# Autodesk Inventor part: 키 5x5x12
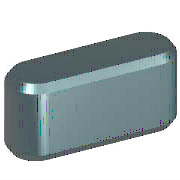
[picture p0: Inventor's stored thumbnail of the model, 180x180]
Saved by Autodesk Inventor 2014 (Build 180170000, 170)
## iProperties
IsCustomPart: 1
Created: 2012-02
Part Number: 키 5x5x12
Material: 강철, 연강
Description: 키 및 해당 키홈
Document SubType Name: Modeling
Standard: KS B 1311
Designer: mduedu
Standards Organization: KS
Language: ko-KR
Size Designation: 5 x 5 x 12
Categories: <MemberInstance><Categories><Category DisplayName="샤프트 부품" InternalName="7f7aeb1f-a693-4053-b835-cee3144e0d98" Mnemonic="SHFT"><Category DisplayName="키" Interna
Density: 1 g/cm^3
Appearance: Yellow
Author: mduedu
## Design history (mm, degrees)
sketch "스케치1"
  geometry: L1 (2.5, 2.5)-(9.5, 2.5); L2 (9.5, -2.5)-(2.5, -2.5); L3 (0, 9.4)-(0, -7.4) reference; L4 (-5, 0)-(30, 0) reference; L5 (12, 0)-(12, 7); A1 r 2.5 centre (2.5, 0) between (2.5, 2.5) and (2.5, -2.5); A2 r 2.5 centre (9.5, 0) between (9.5, -2.5) and (9.5, 2.5)
  constraints: 6 end point, 5 point on circle, 4 tangent, 3 point on line, 2 centre point, 1 horizontal, 1 parallel, 1 perpendicular
  dimensions: "d0" = 2.5 radius of A1 (= 0.5 x PB); "d13" = 2.5 radius of A2 (= 0.5 x PB); "d14" = 12 distance between parallel lines of L5 L3 (= NLG)
extrude "본체1" new body sketch "스케치1" taper "d3" = 0 deg; stored distance "d4" = 10
workplane "Work Plane3"
body "Solid1"
workplane "Work Plane1"
workplane "Work Plane2"
chamfer "모따기1" distance "d8" = 0.4 (= PHH); stored, may be unused: second distance "d9" = 0.4 (= PHH), angle "d15" = 45 deg
other parameters: "d1" = -3 (= -PNT), "d2" = 2 (= PH - PNT), "NLG" = 12 [user parameter; used in 3 equation terms], "PB" = 5 [user parameter; used in 2 equation terms], "PNT" = 3 [user parameter; used in 2 equation terms], "PH" = 5 [user parameter; used in 1 equation term], "PHH" = 0.4 [user parameter; used in 2 equation terms], "d10" = 0, "d16" = 0, "d17" = 0, "d18" = 0, "WDMIN" = 12 [user parameter], "PLB2" = 12 (= NLG) [user parameter], "WDMAX" = 17 [user parameter], "PLB1" = 12 (= NLG) [user parameter], "RR" = 0.16 [user parameter], "PUEB" = 2.3 [user parameter]
